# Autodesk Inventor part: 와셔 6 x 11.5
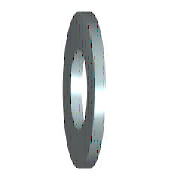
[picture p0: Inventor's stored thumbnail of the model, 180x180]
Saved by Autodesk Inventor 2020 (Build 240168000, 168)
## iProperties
Created: 2012-02
Part Number: 와셔 6 x 11.5
Material: 강철, 연강
Description: 평면 와셔
Document SubType Name: Modeling
Standard: KS B 1326
Designer: mduedu
Standards Organization: KS
Language: ko-KR
Size Designation: 6x11.5
Categories: <MemberInstance><Categories><Category DisplayName="조임쇠" InternalName="e4da775c-781d-43d5-af7c-5136215cf5a6" Mnemonic="FSTN"><Category DisplayName="와셔" InternalN
Density: 7.86 g/cm^3
Mass: 0.901687 g
Surface Area: 2.33373 cm^2
Volume: 0.114718 cm^3
Appearance: 주황색
IsCustomPart: 1
Author: mduedu
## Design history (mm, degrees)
sketch "스케치"
  geometry: C1 r 5.75 at (0, 0); C2 r 3.2 at (0, 0); 1 further point
  constraints: 2 centre point, 2 coincident
  dimensions: "d0" = 6.4 diameter of C2 (= SD1); "d1" = 11.5 diameter of C1 (= SD2)
extrude "본체" new body sketch "스케치" distance "d2" = 1.6 (= SD); taper "d3" = 0 deg
workaxis "Work Axis1"
workplane "Work Plane1"
body "Solid1"
other parameters: "SD1" = 6.4 [user parameter; used in 1 equation term], "SD2" = 11.5 [user parameter; used in 1 equation term], "SD" = 1.6 [user parameter; used in 1 equation term], "d4" = 0, "d5" = 0, "d6" = 0, "d7" = 0, "NND" = 6 [user parameter]
